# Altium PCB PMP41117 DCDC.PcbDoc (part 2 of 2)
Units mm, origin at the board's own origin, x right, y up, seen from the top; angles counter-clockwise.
Board outline 26.81 x 27.2 mm, 4 copper layers (Top Layer, Signal Layer 1, Signal Layer 2, Bottom Layer), stack 1.016 mm thick; 79 components, 59 nets, 285 pads, 212 vias.
Unrouted connection lines stored in the file: 2.
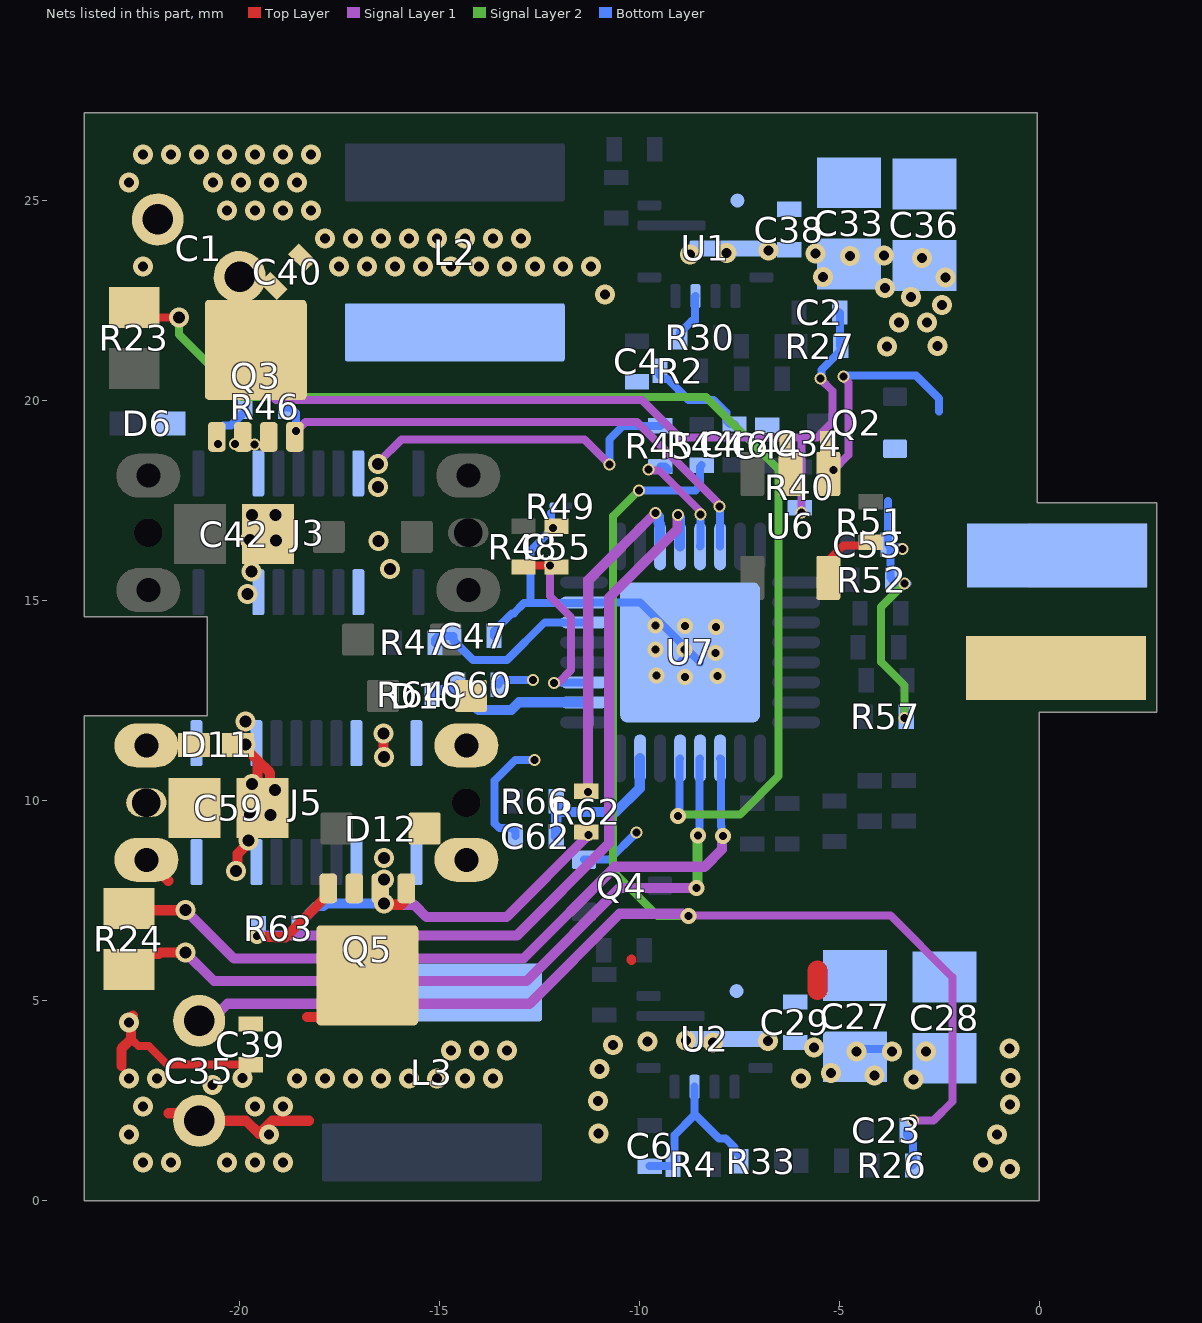
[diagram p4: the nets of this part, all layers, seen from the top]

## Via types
v1: diameter 0.5, hole 0.25, Top Layer to Bottom Layer, 93 vias
v2: diameter 0.3, hole 0.2, Top Layer to Bottom Layer, tented both sides, 69 vias
v3: diameter 0.5, hole 0.3, Top Layer to Bottom Layer, tented both sides, 27 vias
v4: diameter 0.4, hole 0.2, Top Layer to Bottom Layer, tented both sides, 16 vias
v5: diameter 0.5, hole 0.25, Top Layer to Bottom Layer, tented both sides, 7 vias

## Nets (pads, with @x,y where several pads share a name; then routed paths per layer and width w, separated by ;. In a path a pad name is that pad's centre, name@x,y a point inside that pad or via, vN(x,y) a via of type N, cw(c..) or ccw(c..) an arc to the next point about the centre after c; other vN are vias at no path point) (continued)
RTN_B: C59.2 D10.1 D11.2 D12.1 J5.1 J5.2 J5.3 J5.4 J5.@-22.318,9.949 J5.A1 J5.A12 J5.B1 J5.B12 R24.2 U7.11 | length 19.6
  Top Layer w0.254: R24.2@-22.757,7.301 -22.715,7.26 v3(-21.341,7.26) ; J5.4@-22.318,8.519 -22.297,8.519 -21.773,7.996
  Signal Layer 1 w0.254: v3(-21.341,7.26) -20.132,6.051 -12.892,6.051 -10.597,8.346 -8.362,8.346 -7.928,8.78 -7.928,9.092 v4(-7.9,9.12)
  Bottom Layer w0.2: U7.11@-7.977,11.057 -7.958,11.038 -7.958,10.517 -7.948,10.507 -7.948,9.364 -7.938,9.354 -7.938,9.158 v4(-7.9,9.12)
SGND: C1.1 C4.2 C6.2 C27.2 C28.2 C29.2 C33.2 C34.2 C35.1 C36.2 C38.2 C39.2 C40.2 C44.2 C46.2 C47.2 C53.1 C55.2 C60.2 C62.2 pad.N@0.42,13.318 Q2.2 Q4.2 R2.1 R4.1 R23.1 R24.1 R30.1 R33.1 R49.2 R52.1 R57.1 U1.3 U1.9 U2.3 U2.9 U6.2 U7.12 U7.13 U7.23 U7.33 | length 89.5
  Top Layer w0.2: R23.1@-22.623,22.326 -22.377,22.08 v3(-21.502,22.08) ; -22.608,3.956 -22.511,3.859 -22.253,3.859 -21.791,3.398 C39.2@-19.711,3.398 ; v1@-19.808,3.156 C39.2@-19.808,3.398 ; C34.2@-6.303,18.94 -6.263,18.899 -6.263,18.21 U6.2@-6.222,18.169 ; -5.536,5.262 -5.464,5.19
  Top Layer w0.254: -22.944,3.364 -22.944,3.793 -22.703,4.034 -22.703,4.583 v1@-22.655,4.63 ; R24.1@-22.757,5.781 -22.374,6.164 -22.006,6.164 -21.971,6.199 v3(-21.34,6.199) ; -21.762,2.182 -21.188,2.182 C35.1@-21,1.995 -19.827,1.995 -19.501,1.668 -19.174,1.995 -18.253,1.995 ; -10.193,6.022 -10.191,6.025
  Top Layer w0.5: -5.536,5.262 -5.536,5.758
  Signal Layer 1 w0.254: v3(-21.34,6.199) -20.629,5.488 -12.813,5.488 -10.482,7.819 v4(-8.564,7.819)
  Signal Layer 2 w0.2: v3(-21.502,22.08) -21.502,21.649 -19.946,20.093 -8.327,20.093 -6.515,18.282 -6.515,10.612 -7.473,9.655 -8.991,9.655 v4(-9.026,9.619) ; v2(-3.369,15.423) -3.953,14.838 -3.953,13.47 -3.367,12.883 v2(-3.367,12.069)
  Signal Layer 2 w0.254: v4(-8.564,7.819) -8.544,7.839 -8.544,9.104 v4(-8.524,9.124)
  Bottom Layer w0.2: C47.2@-13.629,14.117 -13.629,14.231 -13.176,14.684 -13.134,14.684 -12.876,14.942 -12.712,14.942 ; C60.2@-13.521,12.898 -13.521,12.925 -13.431,13.016 v2(-12.647,13.016) ; C62.2@-13.09,9.11 -13.09,9.225 -13.181,9.315 -13.496,9.315 -13.613,9.432 -13.613,10.497 -13.096,11.014 v2(-12.621,11.014) ; -12.206,17.195 -12.206,16.895 -12.153,16.842 v2(-12.153,16.815) -12.712,16.255 -12.712,14.942 ; Q4.2@-11.38,8.521 -10.75,8.521 v2(-10.067,9.204) ; C6.2@-9.736,0.861 -9.159,0.861 -9.159,0.89 -9.119,0.93 -9.119,1.636 -8.613,2.141 U2.3@-8.613,2.847 ; R2.1@-9.487,20.744 -9.487,20.643 -9.39,20.546 -9.29,20.546 -8.762,20.019 -8.137,20.019 -7.82,19.702 -7.82,19.504 -7.729,19.414 C46.2@-7.615,19.414 ; v4(-9.026,9.619) -8.993,9.653 -8.993,11.041 U7.13@-8.977,11.057 ; U7.33@-8.977,13.457 U7.33@-8.727,13.707 ; R30.1@-8.976,21.588 -8.976,21.702 -8.693,21.985 -8.606,21.985 -8.606,22.012 -8.603,22.012 -8.603,22.6 U1.3@-8.591,22.612 ; -8.613,2.165 -8.003,1.554 -7.836,1.554 -7.613,1.33 -7.613,1.262 -7.452,1.102 R33.1@-7.452,0.988 ; v4(-8.524,9.124) -8.496,9.152 -8.496,11.038 U7.12@-8.477,11.057 ; U7.33@-8.477,13.457 U7.33@-8.727,13.707 ; C27.2@-4.601,3.597 -4.415,3.784 v1@-3.799,3.784 ; -3.779,17.487 C53.1@-3.779,16.397 C53.1@-3.719,16.338 ; R52.1@-3.66,15.503 -3.584,15.428 v2@-3.287,15.428 ; R52.1@-3.66,15.519 -3.719,15.578 C53.1@-3.719,16.338 ; v2(-3.417,16.288) -3.444,16.288 -3.483,16.327 -3.709,16.327 C53.1@-3.719,16.338 ; R57.1@-3.325,12.098 R57.1@-3.325,12.212 ; -12.712,14.942 -11.392,14.942 U7.23@-11.377,14.957 -9.977,14.957 U7.33@-8.727,13.707
  other v1: -0.724,0.787 -22.408,0.956 -21.708,0.956 -20.308,0.956 -19.608,0.956 -18.908,0.956 -1.408,0.956 -22.758,1.656 -19.258,1.656 -1.058,1.656 -22.408,2.356 -19.608,2.356 -18.908,2.356 -0.726,2.407 -20.672,2.887 -3.142,3.023 -22.758,3.056 -22.058,3.056 -18.558,3.056 -17.858,3.056 -17.158,3.056 -16.458,3.056 -15.758,3.056 -15.058,3.056 -14.358,3.056 -13.658,3.056 -5.958,3.056 -0.717,3.064 -19.918,3.07 -4.122,3.126 -5.198,3.188 -4.568,3.724 -3.683,3.724 -2.835,3.733 -14.708,3.756 -14.008,3.756 -13.308,3.756 -0.744,3.804 -5.63,3.832 -9.795,3.976 -22.758,4.456 -3.804,21.349 -2.545,21.367 -3.508,21.956 -2.808,21.956 -2.425,22.389 -3.207,22.588 -10.858,22.656 -3.86,22.811 -2.347,23.079 -5.408,23.086 -22.408,23.356 -17.508,23.356 -16.808,23.356 -16.108,23.356 -15.408,23.356 -14.708,23.356 -14.008,23.356 -13.308,23.356 -12.608,23.356 -11.908,23.356 -11.208,23.356 -2.928,23.569 -4.731,23.614 -3.875,23.626 -8.731,23.656 -7.822,23.69 -5.586,23.683 -6.768,23.759 -17.858,24.056 -17.158,24.056 -16.458,24.056 -15.758,24.056 -15.058,24.056 -14.358,24.056 -13.658,24.056 -12.958,24.056 -20.308,24.756 -19.608,24.756 -18.908,24.756 -18.208,24.756 -22.758,25.456 -20.658,25.456 -19.958,25.456 -19.258,25.456 -18.558,25.456 -22.408,26.156 -21.708,26.156 -21.008,26.156 -20.308,26.156 -19.608,26.156 -18.908,26.156 -18.208,26.156
  other v4: -8.849,13.096 -8.045,13.113 -9.571,13.129 -8.095,13.695 -9.587,13.777 -8.866,13.777 -8.078,14.343 -8.849,14.359 -9.595,14.383
  other v5: -11.01,1.677 -11.027,2.495 -10.992,3.285 -10.656,3.893 -8.157,3.953 -8.823,3.997 -6.782,3.985
VCC_PD: R51.1 U6.5 | length 1.4
  Top Layer w0.2: U6.5@-5.272,15.569 -5.272,15.749 -5.272,15.999 -4.91,16.361 -4.886,16.361 -4.886,16.378 R51.1@-4.505,16.378 ; R51.1@-4.295,16.448 -4.286,16.457 R51.1@-4.212,16.457
VO_A: C1.2 C2.1 C40.1 L2.2 Q3.5 Q3.6 Q3.7 Q3.8 Q3.9@-19.584,21.27 R27.2 R40.2 | length 22.9
  Signal Layer 1 w0.2: C1.2@-19.986,23.094 -19.986,20.916 -19.082,20.012 -9.925,20.012 -8.989,19.076 -5.944,19.076 -5.937,19.069 v2(-5.937,17.208) ; -5.979,19.076 -5.546,19.076 -5.17,19.453 -5.17,20.245 -5.465,20.54 v2(-5.465,20.547)
  Bottom Layer w0.2: v2@-5.465,20.54 v2(-5.465,20.547) -5.446,20.566 -5.446,20.765 -4.962,21.25 R27.2@-4.962,21.364 -4.975,21.377 -4.975,22.19 C2.1@-4.988,22.203
VO_ACDC: C27.1 C28.1 C29.1 C33.1 C34.1 C36.1 C38.1 pad.N@0.442,16.124 U1.8 U2.8 U6.1 | length 6.4
  Top Layer w0.2: C34.1@-5.287,18.94 -5.28,18.932 -5.28,18.177 U6.1@-5.272,18.169 ; U6.1@-5.272,18.186 -5.196,18.262 v2(-5.145,18.262)
  Signal Layer 1 w0.2: v2(-5.145,18.262) -4.77,18.637 -4.77,20.454 -4.894,20.578 v2(-4.894,20.605)
  Bottom Layer w0.2: v2(-4.894,20.605) -4.875,20.624 -4.804,20.624 -4.799,20.629 -3.079,20.629 -2.506,20.056 -2.506,19.728
VO_B: C23.1 C35.2 C39.1 L3.2 Q5.5 Q5.6 Q5.7 Q5.8 Q5.9@-16.797,5.633 R26.2 R44.2 | length 42.6
  Top Layer w0.254: -18.298,4.591 -17.909,4.591 -17.711,4.789 -17.711,4.847 Q5.9@-17.608,4.95 ; Q5.9@-17.569,4.861 -17.569,4.732 -17.255,5.046 -17.255,5.175 Q5.9@-17.209,5.221 ; Q5.9@-17.209,5.092 Q5.9@-17.209,5.221 ; Q5.9@-17.209,5.35 Q5.9@-17.209,5.221 ; Q5.9@-17.098,5.461 -16.926,5.633 Q5.9@-16.797,5.633 ; Q5.9@-17.033,5.396 Q5.9@-17.209,5.221
  Signal Layer 1 w0.2: v4@-8.762,7.126 -3.712,7.126 -2.17,5.584 -2.17,2.473 -2.644,1.999 v2(-3.153,1.999)
  Signal Layer 1 w0.254: C35.2@-21,4.495 -20.717,4.495 -20.29,4.921 -12.737,4.921 -10.489,7.17 -8.921,7.17 -8.9,7.148 -8.796,7.148 v4(-8.768,7.12)
  Signal Layer 2 w0.2: v2(-10.003,17.755) -10.011,17.755 -10.649,17.116 -10.649,8.227 -9.542,7.12 v4(-8.768,7.12)
  Signal Layer 2 w0.254: C35.2@-21,4.495 C35.2@-20.99,4.485
  Bottom Layer w0.2: v2(-10.003,17.755) -9.307,17.755 -9.306,17.754 -8.596,17.754 -8.478,17.871 -8.478,18.344 R44.2@-8.438,18.384 ; C23.1@-3.302,1.757 -3.302,1.643 -3.157,1.498 -3.157,0.884 R26.2@-3.162,0.878
  Bottom Layer w0.254: C35.2@-21,4.495 C35.2@-20.99,4.485
VOUT1: R45.1 U7.29 | length 2.9
  Signal Layer 1 w0.2: v2(-9.766,18.277) -9.747,18.258 -9.495,18.258 -8.483,17.246 -8.483,17.168 v2(-8.464,17.149)
  Signal Layer 2 w0.2: v2@-8.483,17.168 v2(-8.464,17.149)
  Bottom Layer w0.2: R45.1@-9.468,18.354 -9.353,18.354 R45.1@-9.263,18.264 ; U7.29@-8.483,16.364 U7.29@-8.477,16.357 -8.47,16.364 -8.47,17.143 v2(-8.464,17.149)
VOUT1G: Q3.4 R46.2 U7.30 | length 13.4
  Signal Layer 1 w0.2: v2(-18.573,19.239) -18.344,19.467 -10.051,19.467 -8.039,17.454 -8.039,17.426 -7.989,17.376 v2(-7.989,17.348)
  Bottom Layer w0.2: R46.2@-18.838,19.843 -18.838,19.824 -18.705,19.824 -18.573,19.691 v2(-18.573,19.239) ; v2(-7.989,17.348) -7.983,17.343 -7.983,16.363 U7.30@-7.977,16.357
VOUT2: R62.1 U7.27 | length 8.6
  Signal Layer 1 w0.254: v2(-11.277,10.213) -11.277,11.912 -11.271,11.917 -11.271,15.509 v2(-9.59,17.19)
  Bottom Layer w0.254: v2(-9.59,17.19) -9.59,17.177 -9.511,17.098 -9.511,16.939 -9.486,16.914 -9.486,16.366 U7.27@-9.477,16.357
VOUT2G: Q5.4 R63.2 U7.28 | length 21.9
  Top Layer w0.254: v4(-19.549,6.619) -19.521,6.591 -19.103,6.591 -19.095,6.583 -18.841,6.583 -17.772,7.653 Q5.4@-17.772,7.808
  Signal Layer 1 w0.254: v4(-19.549,6.619) -19.545,6.623 -13.062,6.623 -10.747,8.938 -10.747,15.079 -9.043,16.783 -9.043,17.128 v2(-9.034,17.137)
  Bottom Layer w0.254: v2(-9.034,17.137) -9.034,17.125 -8.986,17.076 -8.986,16.366 U7.28@-8.977,16.357
VOUT_A: C42.1 D6.1 J3.A4 J3.A9 J3.B4 J3.B9 Q3.1 Q3.2 Q3.3 R45.2 R46.1 | length 11
  Top Layer w0.2: v3(-19.679,17.136) -19.679,16.563 v3(-19.732,16.51) -19.087,16.51 v3(-19.079,16.503)
  Signal Layer 1 w0.2: v3(-16.525,18.417) -16.525,18.445 -15.941,19.029 -11.368,19.029 -10.765,18.425 v2@-10.765,18.399
  Bottom Layer w0.2: v2(-20.532,18.916) -20.512,18.935 -20.512,19.345 -20.492,19.366 -20.387,19.366 -20.387,19.379 -20.204,19.379 -19.854,19.729 R46.1@-19.854,19.843 ; v2(-10.738,18.399) -10.738,19.033 -10.401,19.37 R45.2@-9.468,19.37
  other v2: -20.098,18.915 -19.618,18.906
  other v3: -19.795,15.165 -19.689,15.73 -16.23,15.794 -16.518,16.495 -19.087,17.136 -16.534,17.843
VOUT_B: C59.1 D11.1 J5.A4 J5.A9 J5.B4 J5.B9 Q5.1 Q5.2 Q5.3 R62.2 R63.1 | length 16.9
  Top Layer w0.254: v3(-20.084,8.242) -20.037,8.289 -20.037,8.673 v3@-19.771,8.939 ; D11.1@-20.027,11.394 -19.848,11.394 v3(-19.843,11.399) ; D11.1@-19.927,11.394 -19.542,11.009 ; v3(-19.771,9.006) v3@-19.771,8.939 ; v3(-19.73,9.657) C59.1@-19.684,9.703 ; v3(-19.684,10.411) C59.1@-19.684,9.703 ; C59.1@-19.613,10.34 -19.542,10.411 -19.542,11.009 ; Q5.2@-16.472,7.808 -16.426,7.762 -16.426,7.475 v3(-16.379,7.429) -16.347,7.397 -15.949,7.397 -15.871,7.475 -15.871,7.759 Q5.1@-15.822,7.808 ; v3(-16.393,11.676) -16.387,11.669 -16.387,11.091 v3(-16.381,11.085) ; v3@-19.771,8.939 -19.771,9.462 -19.653,9.579 -19.607,9.626 C59.1@-19.416,9.817 ; C59.1@-19.684,9.703 -19.57,9.817 C59.1@-19.416,9.817 ; -19.542,11.009 -19.225,10.693 -19.225,10.008 C59.1@-19.416,9.817
  Signal Layer 1 w0.254: v3(-16.379,8.027) v3(-16.379,7.429) -16.347,7.397 -15.626,7.397 -15.32,7.091 -13.313,7.091 -11.278,9.126 v2@-11.264,9.126
  Bottom Layer w0.254: R63.1@-18.501,6.813 -18.501,6.927 -18.056,7.372 -17.889,7.372 -17.832,7.429 -17.44,7.429 v3(-16.379,7.429)
  other v2: -11.266,9.138
  other v3: -16.382,8.566 -19.21,9.64 -19.109,10.27 -19.838,11.974
WCC1_A: C47.1 R47.1 U7.22 | length 4.6
  Bottom Layer w0.2: R47.1@-15.104,13.945 -15.104,14.026 -15.014,14.117 C47.1@-14.645,14.117 -14.645,14.003 -14.154,13.512 -13.304,13.512 -12.36,14.457 U7.22@-11.377,14.457
WCC1_B: C60.1 R64.1 U7.18 | length 4.2
  Bottom Layer w0.254: R64.1@-15.173,12.663 -15.173,12.7 -15.11,12.763 C60.1@-14.652,12.763 ; C60.1@-14.537,12.898 -14.588,12.847 -14.588,12.749 -14.503,12.749 -14.02,12.266 -13.195,12.266 -13.004,12.457 U7.18@-11.377,12.457
WCC2_A: C55.1 R48.1 U7.19 | length 4.9
  Top Layer w0.2: R48.1@-12.892,15.84 -12.858,15.874 v2(-12.229,15.874) -12.229,15.814 C55.1@-12.195,15.78
  Signal Layer 1 w0.2: v2(-12.229,15.874) -12.229,15.111 -11.701,14.583 -11.701,14.148 -11.698,14.145 -11.698,13.772 -11.701,13.769 -11.701,13.265 -12.01,12.956 -12.114,12.956 v2(-12.133,12.937)
  Bottom Layer w0.2: v2(-12.133,12.937) -12.123,12.947 -11.387,12.947 U7.19@-11.377,12.957
WCC2_B: C62.1 R66.1 U7.15 | length 4
  Bottom Layer w0.254: C62.1@-12.074,9.11 -12.073,9.112 -12.073,9.804 R66.1@-12.072,9.982 R66.1@-12.072,9.982 ; R66.1@-12.072,9.868 -11.922,9.718 -10.577,9.718 -9.986,10.31 -9.986,11.048 U7.15@-9.977,11.057
pads on no net: J3. J3.A8 J3.B8 J5.@-14.318,9.949 J5.A8 J5.B8 Q3.9@-18.609,21.795 Q3.9@-18.922,20.408 Q3.9@-18.922,21.284 Q3.9@-19.259,21.795 Q3.9@-19.584,20.947 Q3.9@-19.909,21.795 Q3.9@-20.247,20.408 Q3.9@-20.247,21.284 Q3.9@-20.559,21.795 Q5.9@-15.822,5.108 Q5.9@-16.134,5.619 Q5.9@-16.134,6.495 Q5.9@-16.472,5.108 Q5.9@-16.797,5.955 Q5.9@-17.122,5.108 Q5.9@-17.459,5.619 Q5.9@-17.459,6.495 Q5.9@-17.772,5.108 U1.4 U2.4 U6.3 U6.4 U7.25 U7.26

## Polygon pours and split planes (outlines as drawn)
SGND on Bottom Layer "BOTTOM_LAYER_SGND_P208" (solid, remove dead copper, pour order 208): -11.849,24.082 -11.849,19.936 -1.903,19.936 -1.903,24.082
NetC3_2 on Bottom Layer "BOTTOM_LAYER_NETC3_2_P264" (solid, pour order 264): -11.985,26.48 -11.66,26.322 -11.66,25.003 -11.355,24.785 -10.332,24.785 -10.073,24.526 -8.578,24.526 -8.578,24.242 -11.475,24.285 -12.462,24.994 -17.367,24.994 -17.367,26.48
NetC5_2 on Bottom Layer "BOTTOM_LAYER_NETC5_2_P239" (solid, pour order 239): -17.924,1.924 -12.63,1.9 -12.171,2.359 -12.171,4.084 -11.429,4.827 -8.439,4.827 -8.439,4.473 -11.21,4.473 -11.804,3.878 -11.804,0.976 -12.12,0.468 -17.924,0.447
VO_ACDC on Bottom Layer "BOTTOM_LAYER_VO_ACDC_P328" (solid, remove dead copper, pour order 328): -9.621,27.196 -9.6,24.334 -0.373,24.334 -0.373,27.196
SGND on Bottom Layer "BOTTOM_LAYER_SGND_P322" (solid, remove dead copper, pour order 322): -14.178,20.5 -3.128,20.5 -3.128,8.301 -8.33,8.318 -8.33,6.658 -14.178,6.7
SGND on Bottom Layer "BOTTOM_LAYER_SGND_P326" (solid, remove dead copper, pour order 326): -11.595,4.404 -11.595,0.121 -0.275,0.121 -0.275,4.404
VO_ACDC on Bottom Layer "BOTTOM_LAYER_VO_ACDC_P324" (solid, remove dead copper, pour order 324): -9.336,8.361 -9.336,4.555 -0.769,4.555 -0.769,8.361
VO_B on Bottom Layer "BOTTOM_LAYER_VO_B_P323" (solid, remove dead copper, pour order 323): -20.549,5.731 -20.549,6.184 -12.434,6.184 -12.434,4.518 -19.724,4.518 -20.477,3.765 -21.754,3.765 -21.754,5.731
VO_A on Bottom Layer "BOTTOM_LAYER_VO_A_P266" (solid, remove dead copper, pour order 266): -20.638,23.755 -20.638,21.703 -19.736,20.802 -11.769,20.802 -11.638,20.933 -11.638,22.462 -18.509,22.462 -19.234,23.187 -19.234,23.755
SGND on Bottom Layer "BOTTOM_LAYER_SGND_P321" (solid, remove dead copper, pour order 321): -23.866,27.007 -23.866,21.988 -11.516,21.988 -11.516,27.007
SGND on Bottom Layer "BOTTOM_LAYER_SGND_P307" (solid, remove dead copper, pour order 307): -23.563,5.74 -23.563,-0.008 -12.511,-0.008 -12.511,4.371 -21.842,4.371 -21.842,5.74
VO_ACDC on Bottom Layer "BOTTOM_LAYER_VO_ACDC_P306" (solid, remove dead copper, pour order 306): -2.947,26.34 -2.947,4.559 -0.028,4.559 -0.028,26.34
RTN_B on Bottom Layer "BOTTOM_LAYER_RTN_B_P300" (solid, remove dead copper, pour order 300): -15.821,12.343 -15.875,6.727 -13.426,6.727 -13.426,12.343 -14.632,12.343
RTN_B on Bottom Layer "BOTTOM_LAYER_RTN_B_P295" (solid, remove dead copper, pour order 295): -23.866,13.17 -23.866,6.448 -20.869,6.448 -20.869,13.17
RTN_A on Bottom Layer "BOTTOM_LAYER_RTN_A_P293" (solid, remove dead copper, pour order 293): -15.766,19.018 -13.375,19.018 -13.375,14.852 -13.639,14.589 -15.766,14.589
VOUT_A on Bottom Layer "BOTTOM_LAYER_VOUT_A_P279" (solid, remove dead copper, pour order 279): -21.885,20.385 -21.885,14.224 -15.361,14.224 -15.361,14.952 -15.361,17.617 -15.349,17.629 -15.349,20.385
RTN_A on Bottom Layer "BOTTOM_LAYER_RTN_A_P290" (solid, remove dead copper, pour order 290): -23.765,21.277 -23.765,14.711 -20.83,14.711 -20.83,15.432 -20.83,16.882 -20.83,18.798 -21.332,18.798 -21.332,20.991 -21.589,21.247 -23.731,21.247
VOUT_B on Bottom Layer "BOTTOM_LAYER_VOUT_B_P286" (solid, remove dead copper, pour order 286): -21.317,13.135 -21.317,6.378 -15.418,6.378 -15.418,12.669 -15.885,13.135
no net on Bottom Layer "BOTTOM_LAYER_NONET_P285" (solid, remove dead copper, shelved, pour order 285): -7.031,22.4 -5.586,23.845 -5.586,23.91 -5.309,23.91 -5.119,23.72 -5.119,22.174 -6.047,22.174 -6.334,21.888
no net on Bottom Layer "BOTTOM_LAYER_NONET_P280" (solid, remove dead copper, shelved, pour order 280): 29.094,21.719 29.094,26.189 29.16,26.256 31.398,26.256 31.493,26.16 31.493,24.794 32.235,24.794 32.278,24.751 32.278,21.662 29.109,21.662 29.109,26.226 29.687,26.226 29.701,26.24 29.123,26.24 29.123,24.762 32.25,21.634
no net on Top Layer "Default Coverlay 2 Top" (split plane): -12.047,32.719 -11.031,32.719 -11.031,-4.531 -12.03,-4.531
no net on Top Layer "Default Coverlay 2 Bottom" (split plane): -12.047,32.719 -11.031,32.719 -11.031,-4.531 -12.03,-4.531
SGND on Top Layer "TOP_LAYER_SGND_P269" (solid, remove dead copper, pour order 269): -9.66,26.905 -9.66,19.845 -3.023,19.845 -3.023,5.413 -9.894,5.413 -9.894,0.208 -0.071,0.208 -0.05,26.905
SGND on Top Layer "TOP_LAYER_SGND_P292" (solid, remove dead copper, pour order 292): -15.354,5.458 -15.354,4.255 -15.696,3.751 -21.852,3.754 -21.814,0.12 -9.862,0.12 -9.835,5.458
SGND on Top Layer "TOP_LAYER_SGND_P291" (solid, remove dead copper, pour order 291): -13.141,19.395 -3.163,19.395 -3.163,5.649 -13.141,5.649
VO_B on Top Layer "TOP_LAYER_VO_B_P261" (solid, remove dead copper, pour order 261): -21.85,5.953 -21.85,3.676 -15.532,3.676 -15.532,5.953
RTN_A on Top Layer "TOP_LAYER_RTN_A_P288" (solid, remove dead copper, pour order 288): -15.268,21.294 -15.268,13.617 -13.21,13.617 -13.21,21.294
RTN_B on Top Layer "TOP_LAYER_RTN_B_P287" (solid, remove dead copper, pour order 287): -15.326,13.252 -15.326,6.19 -15.281,6.145 -13.448,6.145 -13.269,6.325 -13.269,13.171 -13.349,13.252
VO_A on Top Layer "TOP_LAYER_VO_A_P268" (solid, remove dead copper, pour order 268): -19.684,23.784 -21.02,23.784 -21.02,20.263 -20.745,19.987 -18.263,19.987 -18.263,22.621
SGND on Top Layer "TOP_LAYER_SGND_P284" (solid, remove dead copper, pour order 284): -23.795,26.93 -23.795,19.891 -9.416,19.891 -9.416,26.93
VOUT_A on Top Layer "TOP_LAYER_VOUT_A_P283" (solid, remove dead copper, pour order 283): -21.319,21.226 -21.319,14.26 -21.293,14.235 -15.361,14.235 -15.361,14.962 -15.361,17.627 -15.349,17.639 -15.349,21.226 -21.358,21.226
RTN_A on Top Layer "TOP_LAYER_RTN_A_P275" (solid, remove dead copper, pour order 275): -23.743,21.283 -23.743,14.286 -23.765,14.263 -20.83,14.263 -20.83,15.442 -20.353,15.919 -20.353,17.37 -20.308,17.415 -21.332,18.439 -21.332,21.283
SGND on Top Layer "TOP_LAYER_SGND_P274" (solid, remove dead copper, pour order 274): -23.66,0.13 -21.724,0.13 -21.724,6.306 -23.66,6.306
VOUT_B on Top Layer "TOP_LAYER_VOUT_B_P272" (solid, remove dead copper, pour order 272): -21.989,13.239 -15.421,13.239 -15.421,6.13 -20.655,6.13 -20.655,11.596 -20.9,11.842 -21.989,11.842 -21.989,13.219
RTN_B on Top Layer "TOP_LAYER_RTN_B_P271" (solid, remove dead copper, pour order 271): -23.527,11.959 -23.527,6.794 -20.794,6.794 -20.794,8.616 -20.794,8.709 -20.219,9.283 -20.219,11.206 -20.973,11.959 -21.725,11.959
RTN_B on Signal Layer 2 "SIGNAL_LAYER_2_RTN_B_P314" (solid, remove dead copper, pour order 314): -15.911,13.479 -15.911,6.777 -13.462,6.777 -13.462,13.469 -15.899,13.469
RTN_B on Signal Layer 2 "SIGNAL_LAYER_2_RTN_B_P313" (solid, remove dead copper, pour order 313): -23.902,13.219 -23.902,6.498 -20.905,6.498 -20.905,13.219
RTN_A on Signal Layer 2 "SIGNAL_LAYER_2_RTN_A_P312" (solid, remove dead copper, pour order 312): -15.802,19.068 -13.411,19.067 -13.411,14.902 -13.675,14.638 -15.802,14.638
RTN_A on Signal Layer 2 "SIGNAL_LAYER_2_RTN_A_P311" (solid, remove dead copper, pour order 311): -23.801,21.327 -23.801,14.761 -20.866,14.761 -20.866,15.481 -20.866,16.932 -20.866,18.847 -21.368,18.847 -21.368,21.04 -21.625,21.297 -23.767,21.297
VOUT_B on Signal Layer 2 "SIGNAL_LAYER_2_VOUT_B_P310" (solid, remove dead copper, pour order 310): -21.353,13.184 -21.353,6.427 -15.454,6.427 -15.454,12.718 -15.921,13.184
VOUT_A on Signal Layer 2 "SIGNAL_LAYER_2_VOUT_A_P309" (solid, remove dead copper, pour order 309): -21.92,20.434 -21.92,14.274 -15.397,14.274 -15.397,15.001 -15.397,17.667 -15.385,17.679 -15.385,20.434
SGND on Signal Layer 2 "SIGNAL_LAYER_2_SGND_P305" (solid, remove dead copper, pour order 305): -13.213,19.623 -13.213,7.756 -2.881,7.756 -2.881,19.623
SGND on Signal Layer 2 "SIGNAL_LAYER_2_SGND_P301" (solid, pour order 301): -2.749,20.724 -2.749,0.336 -0.352,0.336 -0.352,20.724
SGND on Signal Layer 2 "SIGNAL_LAYER_2_SGND_P299" (solid, remove dead copper, pour order 299): -23.626,27.118 -23.626,20.493 -0.051,20.493 -0.051,27.196 -23.548,27.196
SGND on Signal Layer 2 "SIGNAL_LAYER_2_SGND_P296" (solid, remove dead copper, pour order 296): -23.567,7.434 -23.567,0.228 -2.688,0.228 -2.688,7.434
SGND on Signal Layer 1 "SIGNAL_LAYER_1_SGND_P303" (solid, remove dead copper, pour order 303): -12.704,19.324 -2.974,19.324 -2.974,8.065 -12.695,8.065 -12.695,19.315
SGND on Signal Layer 1 "SIGNAL_LAYER_1_SGND_P327" (solid, pour order 327): -2.785,22.001 -2.785,7.422 -1.162,5.798 -1.162,0.994 -1.162,0.373 -0.238,0.373 -0.238,22.001
SGND on Signal Layer 1 "SIGNAL_LAYER_1_SGND_P304" (solid, remove dead copper, pour order 304): -23.866,27.196 -23.866,21.177 -0.352,21.177 -0.352,27.196
RTN_B on Signal Layer 1 "SIGNAL_LAYER_1_RTN_B_P320" (solid, remove dead copper, pour order 320): -15.902,13.44 -15.902,6.738 -13.453,6.738 -13.453,13.43 -15.89,13.43
RTN_B on Signal Layer 1 "SIGNAL_LAYER_1_RTN_B_P319" (solid, remove dead copper, pour order 319): -23.893,13.18 -23.893,6.459 -20.896,6.459 -20.896,13.18
RTN_A on Signal Layer 1 "SIGNAL_LAYER_1_RTN_A_P318" (solid, remove dead copper, pour order 318): -15.793,19.029 -13.402,19.028 -13.402,14.863 -13.666,14.599 -15.793,14.599
RTN_A on Signal Layer 1 "SIGNAL_LAYER_1_RTN_A_P317" (solid, remove dead copper, pour order 317): -23.793,20.664 -23.793,14.722 -20.857,14.722 -20.857,15.442 -20.857,16.893 -20.857,18.808 -21.36,18.808 -21.36,20.664
VOUT_B on Signal Layer 1 "SIGNAL_LAYER_1_VOUT_B_P316" (solid, remove dead copper, pour order 316): -21.344,13.146 -21.344,6.388 -15.445,6.388 -15.445,12.679 -15.912,13.146
VOUT_A on Signal Layer 1 "SIGNAL_LAYER_1_VOUT_A_P315" (solid, remove dead copper, pour order 315): -21.912,20.395 -21.912,14.235 -15.388,14.235 -15.388,14.962 -15.388,17.628 -15.376,17.64 -15.376,20.395
SGND on Signal Layer 1 "SIGNAL_LAYER_1_SGND_P308" (solid, pour order 308): -19.995,22.443 -19.995,19.986 -8.778,19.986 -8.778,22.558 -19.688,22.558 -19.848,22.398
SGND on Signal Layer 1 "SIGNAL_LAYER_1_SGND_P298" (solid, remove dead copper, pour order 298): -23.564,7.464 -23.564,-0.008 -0.271,-0.008 -0.271,7.507 -20.666,7.507 -23.588,7.507

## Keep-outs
Keep-Out Layer:
  text ".Layer_Name" at -36.375,-70.087 h1.52

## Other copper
Top Layer:
  pour cut-out: -17.369,26.462 -17.369,25.029 -17.334,24.994 -12.621,24.994 -12.454,24.994 -11.498,24.27 -9.552,24.27 -9.552,24.523 -10.1,24.523 -10.369,24.792 -11.366,24.792 -11.678,25.012 -11.678,26.313 -11.907,26.462
  pour cut-out: -17.901,1.943 -12.628,1.943 -12.187,2.385 -12.187,3.745 -11.805,3.745 -11.805,0.853 -12.136,0.522 -17.941,0.522 -17.941,1.936 -17.917,1.96
  pour cut-out: -22.016,22.491 -22.016,21.853 -21.247,21.853 -21.247,22.491
  pour cut-out: -22.01,20.926 -22.01,20.351 -21.31,20.351 -21.31,20.926
  pour cut-out: -22.256,7.696 -22.256,6.983 -20.998,6.983 -20.998,7.696
  pour cut-out: -22.183,6.562 -22.183,5.85 -20.97,5.85 -20.97,6.562
  pour cut-out: -21.789,6.525 -21.789,5.95 -20.913,5.95 -20.913,6.525
  pour cut-out: -21.718,7.69 -21.718,7.063 -20.842,7.063 -20.842,7.69
  pour cut-out: -22.03,22.435 -22.03,21.589 -21.259,21.589 -21.259,22.435
  pour cut-out: -22.029,21.415 -22.029,20.238 -21.243,20.238 -21.243,21.415
  pour cut-out: -9.369,10.594 -9.369,7.491 -8.106,7.491 -8.106,10.594
  text ".Layer_Name" at -36.375,-70.087 h1.52
Signal Layer 1:
  pour cut-out: -17.372,26.435 -17.372,25.002 -17.337,24.967 -12.624,24.967 -12.457,24.967 -11.501,24.243 -9.555,24.243 -9.555,24.496 -10.103,24.496 -10.372,24.765 -11.369,24.765 -11.681,24.985 -11.681,26.286 -11.91,26.435
  pour cut-out: -17.961,1.898 -12.688,1.898 -12.247,2.339 -12.247,3.742 -11.865,3.742 -11.865,0.807 -12.196,0.476 -18.001,0.476 -18.001,1.89 -17.977,1.914
  pour cut-out: -9.329,10.231 -9.329,8.647 -8.29,8.647 -8.29,10.231
  pour cut-out: -23.55,22.489 -23.55,21.087 -20.279,21.087 -20.279,22.489
  pour cut-out: -22.108,20.932 -22.108,20.357 -21.308,20.357 -21.308,20.932
  pour cut-out: -23.543,7.702 -23.543,6.989 -20.996,6.989 -20.996,7.702
  pour cut-out: -23.55,6.718 -23.55,5.855 -20.968,5.855 -20.968,6.718
  pour cut-out: -22,22.429 -22,21.855 -21.244,21.855 -21.244,22.429
Signal Layer 2:
  pour cut-out: -17.352,26.458 -17.352,25.024 -17.318,24.99 -12.605,24.99 -12.437,24.99 -11.482,24.265 -9.536,24.265 -9.536,24.519 -10.084,24.519 -10.353,24.787 -11.349,24.787 -11.662,25.008 -11.662,26.308 -11.891,26.458
  pour cut-out: -17.905,1.918 -12.633,1.918 -12.191,2.359 -12.191,3.592 -11.809,3.592 -11.809,0.828 -12.14,0.496 -17.945,0.496 -17.945,1.91 -17.921,1.934
  pour cut-out: -22.021,22.436 -22.021,21.787 -21.153,21.787 -21.153,22.436
  pour cut-out: -22.015,21 -22.015,20.36 -21.121,20.36 -21.121,21
  pour cut-out: -23.497,7.705 -23.497,5.896 -21.002,5.896 -21.002,7.705
  pour cut-out: -21.759,6.571 -21.759,5.858 -20.974,5.858 -20.974,6.571
  pour cut-out: -23.574,22.402 -23.574,20.433 -21.115,20.433 -21.115,22.402
Bottom Layer:
  pour cut-out: -10.243,0.256 -10.432,0.256 -10.432,1.639 -10.243,1.639
  pour cut-out: -10.479,20.184 -11.381,20.184 -11.381,21.108 -10.479,21.108
  pour cut-out: -21.747,6.567 -21.747,5.854 -20.962,5.854 -20.962,6.567
  pour cut-out: -21.775,7.701 -21.775,6.535 -20.99,6.535 -20.99,7.701
  pour cut-out: -22.003,21.268 -22.003,20.356 -20.971,20.356 -20.971,21.268
  pour cut-out: -22.009,22.432 -22.009,21.786 -20.863,21.786 -20.863,22.432
  pour cut-out: -9.383,11.853 -9.383,7.481 -8.12,7.481 -8.12,11.853
  text ".Layer_Name" at -36.375,-70.087 h1.52

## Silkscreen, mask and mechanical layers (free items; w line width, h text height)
Top Overlay:
  lines w0.127: -8.327,0.496 -8.327,26.671
  text ".Layer_Name" at -36.375,-70.087 h1.52
Bottom Overlay:
  text ".Layer_Name" at -36.375,-70.087 h1.52
Top Paste:
  text ".Layer_Name" at -36.375,-70.087 h1.52
Bottom Paste:
  text ".Layer_Name" at -36.375,-70.087 h1.52
Top Solder:
  region: -5.654,21.235 -5.654,22.237 -8.086,22.237 -8.086,21.235
  region: -22.077,3.41 -22.077,5.513 -23.454,5.513 -23.454,3.41
  region: -21.922,22.685 -21.922,24.35 -23.316,24.35 -23.316,22.685
  region: -22.021,18.899 -22.021,20.564 -23.311,20.564 -23.311,18.899
  region: -17.757,24.278 -17.757,26.789 -23.321,26.789 -23.321,24.278
  region: -8.947,25.164 -8.947,26.829 -11.296,26.829 -11.296,25.164
  rectangle: -9.167,21.484 -7.96,23.833
  rectangle: -5.781,21.076 -0.623,24.554
  rectangle: -14.707,20.365 -9.092,24.115
  rectangle: -17.703,21.667 -12.096,24.516
  rectangle: -9.219,23.603 -2.52,26.826
  rectangle: -2.815,5.208 -0.549,26.836
  rectangle: -23.52,0.505 -18.378,3.516
  rectangle: -14.752,3.068 -12.478,4.383
  rectangle: -18.469,2.267 -12.485,3.511
  rectangle: -11.597,0.508 -8.646,4.45
  rectangle: -6.227,2.62 -0.442,4.986
  rectangle: -7.729,5.674 -3.203,7.877
  rectangle: -14.753,3.947 -0.429,5.359
  text ".Layer_Name" at -36.375,-70.087 h1.52
  text ".Layer_Name" at -36.375,-70.087 h1.52
Bottom Solder:
  rectangle: -8.725,5.064 -7.633,6.523
  rectangle: -2.623,7.689 -0.398,19.885
  rectangle: -6.185,2.453 -0.392,4.215
  rectangle: -2.622,0.544 -0.382,2.703
  rectangle: -11.42,0.661 -10.513,3.495
  rectangle: -9.101,24.813 -0.433,26.842
  rectangle: -7.992,24.415 -0.432,26.13
  rectangle: -1.59,19.633 -0.41,24.469
  rectangle: -7.905,4.748 -0.424,8.073
  text ".Layer_Name" at -36.375,-70.087 h1.52
Drill Guide:
  text ".Layer_Name" at -36.375,-70.087 h1.52
M1 Board Outline:
  lines w0.127: -23.87,27.192 -23.87,14.601 -20.803,14.601 -20.803,12.127 -23.866,12.127 -23.866,-0.008 0.002,-0.008 0.002,12.211 2.94,12.211 2.94,17.446 -0.051,17.446 -0.051,27.196 -23.866,27.196
  text ".Layer_Name" at -36.375,-70.087 h1.52
M2 Board Dimensions:
  rectangle: -51.031,-55.266 -47.856,-52.091
  rectangle: -47.856,-58.441 -38.331,-55.266
  lines w0.178: -51.031,-55.266 -25.631,-55.266 ; -47.856,-58.441 -47.856,-52.091 ; -44.681,-58.441 -44.681,-52.091 ; -38.331,-58.441 -38.331,-52.091 ; -31.981,-58.441 -31.981,-52.091 ; -51.031,-58.441 -25.631,-58.441 -25.631,-52.091 -51.031,-52.091 -51.031,-58.441
  text ".Layer_Name" at -36.375,-70.087 h1.52
M3 3D STEP Top:
  text ".Layer_Name" at -36.375,-70.087 h1.52
M4 3D STEP Bottom:
  text ".Layer_Name" at -36.375,-70.087 h1.52
M5 Assembly Top:
  lines w0.254: -58.448,-71.907 109.192,-71.907 ; -58.448,-66.743 109.243,-66.743 ; -58.448,-61.578 -58.448,-77.072 43.279,-77.072 109.243,-77.072 109.243,-61.578 -58.435,-61.578 -58.435,-77.072 -18.417,-77.072 ; 4.163,-77.072 4.163,-61.578 ; 36.345,-66.743 36.345,-61.578 ; 57.681,-66.743 57.681,-61.578 ; 73.48,-77.237 73.48,-72.085
  text "COMPONENTS MARKED 'DNP' SHOULD NOT BE POPULATED." at -21.732,-56.371 h1.52
  text "ASSEMBLY VARIANT:" at -21.745,-59.305 h1.52
  text ".VariantName" at 4.57,-59.305 h1.52
  text "PCB VIEWED FROM TOP SIDE" at -56.835,-64.935 h1.52
  text "BOARD #:" at 6.068,-64.935 h1.52
  text ".PRJ_Number" at 19.924,-64.935 h1.52
  text "REV:" at 41.374,-64.935 h1.52
  text ".PCB_Rev" at 48.778,-64.935 h1.52
  text "SVN REV:" at 62.659,-64.935 h1.52
  text ".VersionControl_RevNumber" at 75.512,-64.935 h1.52
  text "TID #:" at 6.068,-70.1 h1.52
  text ".TID" at 19.924,-70.1 h1.52
  text "PLOT NAME =" at -56.835,-75.315 h1.52
  text ".plot_File_Name" at -36.375,-75.315 h1.52
  text "GENERATED    :" at 6.119,-75.315 h1.52
  text ".Print_Date" at 28.204,-75.315 h1.52
  text ".Print_Time" at 46.721,-75.315 h1.52
  text "TEXAS INSTRUMENTS" at 78.839,-75.315 h1.52
M6 Assembly Bottom:
  lines w0.254: -58.461,-66.755 109.23,-66.755 ; -58.41,-71.92 109.23,-71.92 ; -22.697,-77.25 -22.697,-72.098 ; -6.899,-66.755 -6.899,-61.591 ; 14.437,-66.755 14.437,-61.591 ; 46.619,-77.085 46.619,-61.591 ; 69.2,-77.085 109.218,-77.085 109.218,-61.591 -58.461,-61.591 -58.461,-77.085 7.503,-77.085 109.23,-77.085 109.23,-61.591
  text "COMPONENTS MARKED 'DNP' SHOULD NOT BE POPULATED." at 103.96,-56.358 h1.52
  text ".VariantName" at 77.442,-59.305 h1.52
  text "ASSEMBLY VARIANT:" at 103.833,-59.305 h1.52
  text ".VersionControl_RevNumber" at -24.729,-64.948 h1.52
  text "SVN REV:" at -11.877,-64.948 h1.52
  text ".PCB_Rev" at 2.004,-64.948 h1.52
  text "REV:" at 9.408,-64.948 h1.52
  text ".PRJ_Number" at 30.859,-64.948 h1.52
  text "BOARD #:" at 44.714,-64.948 h1.52
  text "PCB VIEWED FROM BOTTOM SIDE" at 107.617,-64.948 h1.52
  text ".TID" at 30.859,-70.112 h1.52
  text "TID #:" at 44.714,-70.112 h1.52
  text "TEXAS INSTRUMENTS" at -28.057,-75.328 h1.52
  text ".Print_Time" at 4.062,-75.328 h1.52
  text ".Print_Date" at 22.578,-75.328 h1.52
  text "GENERATED    :" at 44.663,-75.328 h1.52
  text ".plot_File_Name" at 87.158,-75.328 h1.52
  text "PLOT NAME =" at 107.617,-75.328 h1.52
M9 Title Sheet:
  drawing of 57 lines, arcs and shapes, not listed
  text "1" at -32.239,155.846 h1.78
  text "2" at 31.151,155.846 h1.78
  text "3" at 94.38,155.846 h1.78
  text "4" at 158.049,155.846 h1.78
  text "5" at 221.524,155.846 h1.78
  text "6" at 285.151,155.846 h1.78
  text "A" at -61.61,126.814 h1.78
  text "A" at 314.31,126.814 h1.78
  text "B" at -61.61,66.362 h1.78
  text "B" at 314.31,66.362 h1.78
  text "C" at -61.61,6.037 h1.78
  text "C" at 314.31,6.037 h1.78
  text "PROJECT TITLE:" at 237.094,-41.232 h1.14
  text ".PRJ_Title" at 238.364,-44.619 h1.78
  text "DESIGNED FOR:" at 237.094,-48.878 h1.14
  text ".PRJ_Customer" at 238.364,-52.434 h1.78
  text "D" at -61.61,-54.161 h1.78
  text "D" at 314.31,-54.161 h1.78
  text "FILE NAME:" at 237.094,-56.498 h1.14
  text ".PCB_File_Name_No_Path" at 238.364,-59.546 h1.78
  text "Texas Instruments (TI) and/or its licensors do not warrant the accuracy or completeness of this specification" at 110.869,-63.657 h1.14
  text "ENGINEER:" at 237.094,-63.864 h1.14
  text "LAYOUT BY:" at 275.321,-63.864 h1.14
  text "or any information contained therein. TI and/or its licensors do not warrant that this design will meet" at 109.726,-66.518 h1.14
  text ".PRJ_Engineer" at 238.364,-67.801 h1.78
  text ".PCB_Layout" at 276.604,-67.801 h1.78
  text "the specifications, will be suitable for your application or fit for any particular purpose, or will operate in" at 109.726,-69.38 h1.14
  text ".Layer_Name" at -36.375,-70.087 h1.52
  text "ALTIUM DESIGNER VERSION:" at 275.321,-71.738 h1.14
  text "an implementation. TI and/or its licensors do not warrant that the design is production worthy. You should" at 109.726,-72.242 h1.14
  text "completely validate and test your design implementation to confirm the system functionality for your application." at 110.869,-75.103 h1.14
  text ".print_Scale" at 238.364,-75.124 h1.78
  text ".Application_BuildNumber" at 276.604,-75.124 h1.78
  text "1" at -32.239,-80.374 h1.78
  text "2" at 31.151,-80.374 h1.78
  text "3" at 94.38,-80.374 h1.78
  text "4" at 158.049,-80.374 h1.78
  text "5" at 221.524,-80.374 h1.78
  text "6" at 285.151,-80.374 h1.78
M10 Fab Notes:
  drawing of 189 lines, arcs and shapes, not listed
  text "DESIGN INFORMATION" at 263.472,113.166 h1.52
  text "MIN. TRACK WIDTH:" at 247.1,109.81 h1.52
  text "8" at 274.945,109.81 h1.52
  text "MIL" at 278.876,109.81 h1.52
  text "7.874" at 270.719,106.719 h1.52
  text "MIN. CLEARANCE:" at 247.1,106.657 h1.52
  text "MIL" at 278.876,106.657 h1.52
  text "MIN. VIA PAD SIZE:" at 247.1,103.504 h1.52
  text "24" at 274.183,103.504 h1.52
  text "MIL" at 278.876,103.504 h1.52
  text "0.05mm (2MIL)" at 264.753,100.205 h1.52
  text "MINIMUM ANNULAR RING" at 238.738,99.996 h1.52
  text "EXTERNAL" at 282.737,99.996 h1.52
  text "PER" at 243.818,97.199 h1.52
  text "IPC-D-275 CLASS 2 LEVEL C" at 249.406,97.199 h1.52
  text "MIL, HOLES" at 287.207,94.647 h1.52
  text "+/-" at 277.239,94.428 h1.52
  text "+/-" at 298.93,94.428 h1.52
  text "REGISTRATION TOLERANCES:" at 238.738,94.401 h1.52
  text "METAL" at 269.212,94.401 h1.52
  text "5" at 283.848,94.402 h1.52
  text "3" at 305.006,94.402 h1.52
  text "MIL" at 307.959,94.401 h1.52
  text "HOLE SIZE TOLERANCE (UNLESS OTHERWISE SPECIFIED):" at 238.738,91.904 h1.52
  text "+/-" at 298.93,91.831 h1.52
  text "3" at 305.006,91.804 h1.52
  text "MIL" at 307.959,91.804 h1.52
  text "MATERIAL:" at 236.839,88.308 h1.52
  text "FR-4 High Tg" at 261.895,85.043 h1.52
  text "X" at 258.226,84.841 h1.52
  text "FR-4" at 247.532,84.726 h1.52
  text "OTHER" at 285.327,84.726 h1.52
  text "62 MIL (1.6mm) +/-10%" at 255.663,81.093 h1.52
  text "X" at 252.612,81.031 h1.52
  text "THICKNESS:" at 238.738,80.884 h1.52
  text "OTHER" at 288.299,80.884 h1.52
  text "TOLERANCE:" at 238.738,77.371 h1.52
  text "X" at 260.283,77.371 h1.52
  text "ANSI IPC-6012 TYPE 3 CLASS 2" at 264.805,77.371 h1.52
  text "OTHER +/-" at 264.804,73.708 h1.52
  text "BOW & TWIST:" at 238.738,70.021 h1.52
  text "X" at 260.283,70.021 h1.52
  text "ANSI IPC-6012 TYPE 3 CLASS 2" at 264.805,70.021 h1.52
  text "OTHER +/-" at 264.804,66.295 h1.52
  text "DRILLING:" at 236.839,62.977 h1.52
  text "NC_DRILL FILES" at 281.568,60.305 h1.52
  text "REFERENCE:" at 238.738,60.205 h1.52
  text "X" at 255.432,60.203 h1.52
  text "AS SHOWN" at 259.953,60.205 h1.52
  text "X" at 278.317,60.205 h1.52
  text "OTHER" at 289.137,56.592 h1.52
  text "PTH COPPER THICKNESS:" at 238.73,56.502 h1.52
  text "X" at 267.666,56.502 h1.52
  text "20-30 um" at 270.917,56.502 h1.52
  text "BOARD FINISH:" at 236.839,52.753 h1.52
  text "SILKSCREEN:" at 240.781,49.956 h1.52
  text "X" at 265.109,49.956 h1.52
  text "TOP" at 268.081,49.956 h1.52
  text "X" at 278.063,49.956 h1.52
  text "BOTTOM" at 281.06,49.956 h1.52
  text "SILKSCREEN COLOR:" at 240.781,46.014 h1.52
  text "X" at 265.084,46.014 h1.52
  text "WHITE" at 268.081,46.014 h1.52
  text "OTHER" at 281.06,46.014 h1.52
  text "X" at 268.411,42.371 h1.52
  text "GREEN" at 271.408,42.371 h1.52
  text "OTHER" at 287.105,42.371 h1.52
  text "SOLDER RESIST COLOR:" at 240.781,42.196 h1.52
  text "X" at 268.411,38.453 h1.52
  text "MATTE" at 271.408,38.453 h1.52
  text "SEMI-GLOSS" at 287.094,38.436 h1.52
  text "IMMERSION GOLD (ENIG)" at 263.788,34.064 h1.52
  text "ENEPIG" at 297.762,33.881 h1.52
  text "SURFACE FINISH:" at 236.839,33.855 h1.52
  text "X" at 259.267,33.855 h1.52
  text "IMM. TIN/SILVER OR EQUIV" at 245.209,30.368 h1.52
  text "OTHER" at 281.568,30.268 h1.52
  text "ARRAY/PANEL:" at 236.839,26.321 h1.52
  text "CUT AND TRIM PER M1 BOARD OUTLINE" at 263.788,26.112 h1.52
  text "N.C. ROUTE" at 263.788,22.659 h1.52
  text "X" at 281.264,22.659 h1.52
  text "V. SCORE" at 285.785,22.659 h1.52
  text "CERTIFICATION:" at 236.839,19.379 h1.52
  text "MATERIALS AND WORKMANSHIP FOR ALL PCBS" at 255.254,19.379 h1.52
  text "TO MEET OR EXCEED THE REQUIREMENTS OF:" at 255.254,16.99 h1.52
  text "X" at 246.047,13.722 h1.52
  text "ANSI IPC-A-600F CLASS ->" at 249.298,13.722 h1.52
  text "X" at 291.157,13.722 h1.52
  text "2" at 293.951,13.722 h1.52
  text "1" at 285.95,13.684 h1.52
  text "3" at 302.942,13.684 h1.52
  text "X" at 266.671,9.971 h1.52
  text "RoHS" at 269.922,9.971 h1.52
  text "OTHER" at 286.29,9.971 h1.52
  text "PER ORDER" at 296.376,9.971 h1.52
  text "ALL BOARDS MUST MEET OR EXCEED UL94-V0 REQUIREMENTS." at 237.538,6.064 h1.52
  text "PCB MUST BEAR THE UL94V-0 UL REGISTERED MATERIAL ID NUMBER" at 237.538,3.116 h1.52
  text "ADDITIONAL REQUIREMENTS:" at 236.839,-1.187 h1.52
  text "MICROSECTION:" at 238.738,-3.908 h1.52
  text "YES" at 261.744,-3.908 h1.52
  text "REQUIRED" at 283.626,-7.574 h1.52
  text "BARE BOARD ELEC. TEST:" at 238.738,-7.647 h1.52
  text "NONE" at 271.904,-7.647 h1.52
  text "X" at 280.629,-7.647 h1.52
  text "PER ORDER" at 298.662,-7.647 h1.52
  text "XX MIL VIAS REQUIRE NON-CONDUCTIVE FILL AND PLANARIZE" at 243.009,-12.853 h1.5
  text "XX MIL VIAS REQUIRE CONDUCTIVE FILL AND PLANARIZE" at 243.212,-15.494 h1.52
  text "OUTER XX MIL TRACES REQUIRE 50 OHM SINGLE-ENDED IMPEDANCE" at 243.187,-19.644 h1.47
  text "LAYER 2 & 3 (INNER LAYERS) XX MIL WIDE, XX MIL SPACE / TRACES REQUIRE 100 OHM DIFFERENTIAL IMPEDANCE" at 242.984,-25.631 h1.52
  text ".Layer_Name" at -36.375,-70.087 h1.52
M11 Gerber Information:
  lines w0.254: -58.448,-71.907 109.192,-71.907 ; -58.448,-66.743 109.243,-66.743 ; -58.448,-61.578 -58.448,-77.072 43.279,-77.072 109.243,-77.072 109.243,-61.578 -58.435,-61.578 -58.435,-77.072 -18.417,-77.072 ; 4.163,-77.072 4.163,-61.578 ; 36.345,-66.743 36.345,-61.578 ; 57.681,-66.743 57.681,-61.578 ; 73.48,-77.237 73.48,-72.085
  text "ALL ARTWORK VIEWED FROM TOP SIDE" at -56.835,-64.935 h1.52
  text "BOARD #:" at 6.068,-64.935 h1.52
  text ".PRJ_Number" at 19.924,-64.935 h1.52
  text "REV:" at 41.374,-64.935 h1.52
  text ".PCB_Rev" at 48.778,-64.935 h1.52
  text "SVN REV:" at 62.659,-64.935 h1.52
  text ".VersionControl_RevNumber" at 75.512,-64.935 h1.52
  text "LAYER NAME =" at -56.835,-70.087 h1.52
  text "TID #:" at 6.068,-70.1 h1.52
  text ".TID" at 19.924,-70.1 h1.52
  text "PLOT NAME =" at -56.835,-75.315 h1.52
  text ".plot_File_Name" at -36.375,-75.315 h1.52
  text "GENERATED    :" at 6.119,-75.315 h1.52
  text ".Print_Date" at 28.204,-75.315 h1.52
  text ".Print_Time" at 46.721,-75.315 h1.52
  text "TEXAS INSTRUMENTS" at 78.839,-75.315 h1.52
M12 Stackup:
  drawing of 295 lines, arcs and shapes, not listed
  text "Layer" at 198.437,151.743 h1.52
  text "Name" at 208.849,151.743 h1.52
  text "Material" at 232.719,151.743 h1.52
  text "Thickness" at 254.557,151.743 h1.52
  text "Constant" at 271.063,151.743 h1.52
  text "Board Layer Stack" at 285.537,151.743 h1.52
  text "Top Overlay" at 208.849,148.695 h1.52
  text "Top Solder" at 208.849,145.647 h1.52
  text "Solder Resist" at 232.719,145.647 h1.52
  text "0.40mil" at 254.557,145.647 h1.52
  text "3.5" at 271.063,145.647 h1.52
  text "1" at 198.437,142.599 h1.52
  text "Top Layer" at 208.849,142.599 h1.52
  text "2.80mil" at 254.557,142.599 h1.52
  text "Dielectric 1" at 208.849,139.551 h1.52
  text "FR-4 High Tg" at 232.719,139.551 h1.52
  text "5.00mil" at 254.557,139.551 h1.52
  text "4.2" at 271.063,139.551 h1.52
  text "2" at 198.437,136.503 h1.52
  text "Signal Layer 1" at 208.849,136.503 h1.52
  text "1.40mil" at 254.557,136.503 h1.52
  text "Dielectric 2" at 208.849,133.455 h1.52
  text "FR-4 High Tg" at 232.719,133.455 h1.52
  text "21.60mil" at 254.557,133.455 h1.52
  text "4.2" at 271.063,133.455 h1.52
  text "3" at 198.437,130.407 h1.52
  text "Signal Layer 2" at 208.849,130.407 h1.52
  text "1.40mil" at 254.557,130.407 h1.52
  text "Dielectric 3" at 208.849,127.359 h1.52
  text "FR-4 High Tg" at 232.719,127.359 h1.52
  text "5.00mil" at 254.557,127.359 h1.52
  text "4.2" at 271.063,127.359 h1.52
  text "4" at 198.437,124.311 h1.52
  text "Bottom Layer" at 208.849,124.311 h1.52
  text "2.80mil" at 254.557,124.311 h1.52
  text "Bottom Solder" at 208.849,121.263 h1.52
  text "Solder Resist" at 232.719,121.263 h1.52
  text "0.40mil" at 254.557,121.263 h1.52
  text "3.5" at 271.063,121.263 h1.52
  text "Bottom Overlay" at 208.849,118.215 h1.52
  text ".Layer_Name" at -36.375,-70.087 h1.52
M13 Component Bodies Top:
  text ".Layer_Name" at -36.375,-70.087 h1.52
M14 Component Bodies Bottom:
  text ".Layer_Name" at -36.375,-70.087 h1.52
M15 Courtyards Top:
  text ".Layer_Name" at -36.375,-70.087 h1.52
M16 Courtyards Bottom:
  text ".Layer_Name" at -36.375,-70.087 h1.52
Drill Drawing:
  circle w0.254: c85.7,119.984 r0.421
  circle w0.254: c85.7,119.984 r0.702
  lines w0.254: 84.998,100.687 85.349,100.687 85.7,100.336 86.05,100.687 86.401,100.687 86.05,101.038 86.401,101.389 86.05,101.389 85.7,101.74 85.349,101.389 84.998,101.389 85.349,101.038 84.998,100.687 ; 84.998,103.494 86.401,103.494 86.401,104.898 84.998,104.898 84.998,103.494 ; 84.998,108.055 86.401,108.055 85.7,106.652 84.998,108.055 ; 84.998,110.16 85.349,110.16 85.349,109.81 86.05,109.81 86.05,110.16 86.401,110.16 86.401,110.862 86.05,110.862 86.05,111.213 85.349,111.213 85.349,110.862 84.998,110.862 84.998,110.16 ; 84.998,112.967 86.401,112.967 86.401,114.371 84.998,114.371 84.998,112.967 ; 85.279,103.775 86.121,103.775 86.121,104.617 85.279,104.617 85.279,103.775
  lines w0.305: 83.726,99.389 165.805,99.389 ; 83.726,121.493 165.805,121.493 ; 92.307,96.231 92.307,124.651 ; 100.74,96.231 100.74,124.651 ; 116.909,96.231 116.909,124.651 ; 123.491,96.231 123.491,124.651 ; 133.02,96.231 133.02,124.651 ; 151.418,96.231 151.418,124.651 ; 83.726,96.231 165.805,96.231 165.805,124.651 83.726,124.651 83.726,96.231
  text "Symbol" at 85.62,122.44 h1.83
  text "Quantity" at 93.255,122.44 h1.83
  text "Finished Hole Size" at 101.687,122.44 h1.83
  text "Plated" at 117.856,122.44 h1.83
  text "Hole Type" at 124.438,122.44 h1.83
  text "Drill Layer Pair" at 133.967,122.44 h1.83
  text "Hole Tolerance" at 152.365,122.44 h1.83
  text "2" at 93.255,119.283 h1.52
  text "27.95mil (0.710mm)" at 101.687,119.283 h1.52
  text "NPTH" at 117.856,119.283 h1.52
  text "Round" at 124.438,119.283 h1.52
  text "Top Layer - Bottom Layer" at 133.967,119.283 h1.52
  text "85" at 93.255,116.125 h1.52
  text "7.87mil (0.200mm)" at 101.687,116.125 h1.52
  text "PTH" at 117.856,116.125 h1.52
  text "Round" at 124.438,116.125 h1.52
  text "Top Layer - Bottom Layer" at 133.967,116.125 h1.52
  text "D" at 84.978,115.871 h1.4
  text "100" at 93.255,112.967 h1.52
  text "9.84mil (0.250mm)" at 101.687,112.967 h1.52
  text "PTH" at 117.856,112.967 h1.52
  text "Round" at 124.438,112.967 h1.52
  text "Top Layer - Bottom Layer" at 133.967,112.967 h1.52
  text "27" at 93.255,109.81 h1.52
  text "11.81mil (0.300mm)" at 101.687,109.81 h1.52
  text "PTH" at 117.856,109.81 h1.52
  text "Round" at 124.438,109.81 h1.52
  text "Top Layer - Bottom Layer" at 133.967,109.81 h1.52
  text "4" at 93.255,106.652 h1.52
  text "30.00mil (0.762mm)" at 101.687,106.652 h1.52
  text "PTH" at 117.856,106.652 h1.52
  text "Round" at 124.438,106.652 h1.52
  text "Top Layer - Bottom Layer" at 133.967,106.652 h1.52
  text "2" at 93.255,103.494 h1.52
  text "27.95mil (0.710mm)" at 101.687,103.494 h1.52
  text "NPTH" at 117.856,103.494 h1.52
  text "Slot" at 124.438,103.494 h1.52
  text "Top Layer - Bottom Layer" at 133.967,103.494 h1.52
  text "8" at 93.255,100.336 h1.52
  text "23.62mil (0.600mm)" at 101.687,100.336 h1.52
  text "PTH" at 117.856,100.336 h1.52
  text "Slot" at 124.438,100.336 h1.52
  text "Top Layer - Bottom Layer" at 133.967,100.336 h1.52
  text "228 Total" at 93.255,97.179 h1.52
  text "Slot definitions :" at 85.62,94.968 h1.52
  text "Routed Path Length" at 97.068,94.968 h1.52
  text "= Calculated from tool start centre position to tool end centre position." at 110.778,94.968 h1.52
  text "Hole Length" at 97.068,93.705 h1.52
  text "= Routed Path Length + Tool Size = Slot length as defined in the PCB layout" at 105.703,93.705 h1.52
  text ".Layer_Name" at -36.375,-70.087 h1.52
M17 Embedded Cavity:
  text ".Layer_Name" at -36.375,-70.087 h1.52
M18 Embedded Assembly:
  text ".Layer_Name" at -36.375,-70.087 h1.52
M19 Embedded Keepout:
  text ".Layer_Name" at -36.375,-70.087 h1.52

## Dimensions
-51.031,-58.441 to -25.631,-58.441 on M2 Board Dimensions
